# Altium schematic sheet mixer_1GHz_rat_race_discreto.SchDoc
size A4
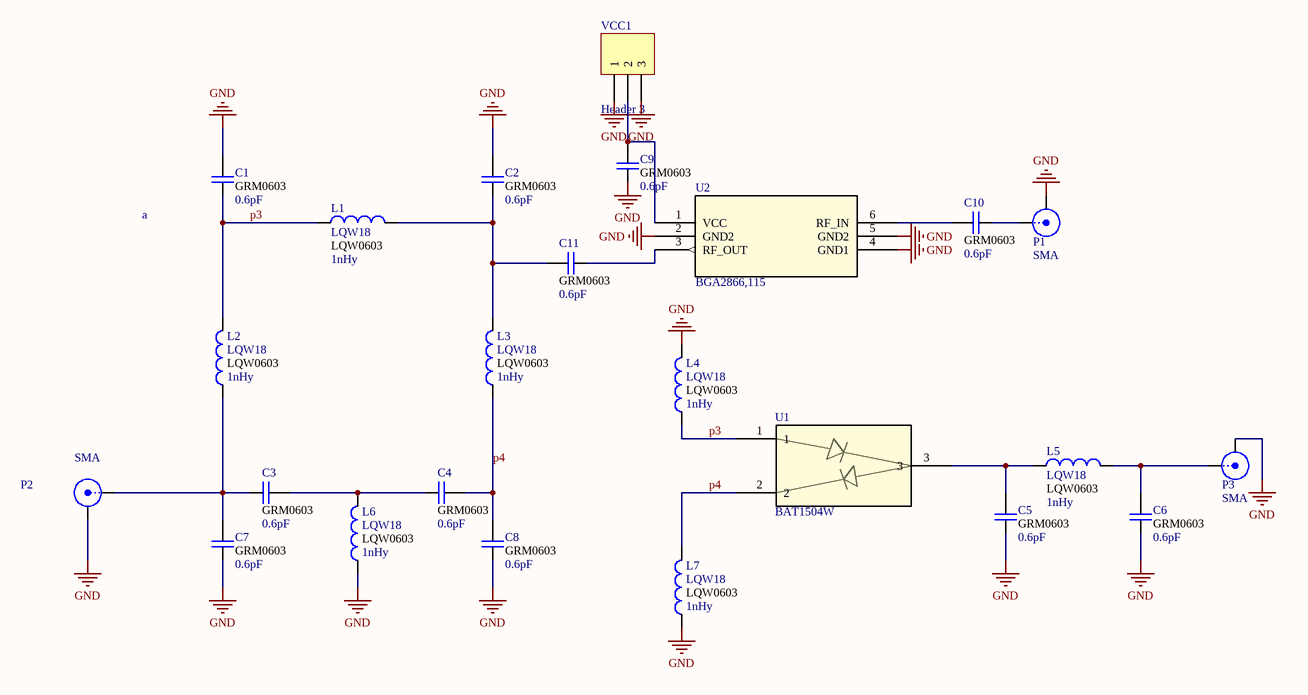
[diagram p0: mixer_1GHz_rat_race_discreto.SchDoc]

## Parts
C1  value 0.6pF  footprint: GRM0603  [CAPC1608X90N]  (hidden comment: Cap 0603)
C2  value 0.6pF  footprint: GRM0603  [CAPC1608X90N]  (hidden comment: Cap 0603)
C3  value 0.6pF  footprint: GRM0603  [CAPC1608X90N]  (hidden comment: Cap 0603)
C4  value 0.6pF  footprint: GRM0603  [CAPC1608X90N]  (hidden comment: Cap 0603)
C5  value 0.6pF  footprint: GRM0603  [CAPC1608X90N]  (hidden comment: Cap 0603)
C6  value 0.6pF  footprint: GRM0603  [CAPC1608X90N]  (hidden comment: Cap 0603)
C7  value 0.6pF  footprint: GRM0603  [CAPC1608X90N]  (hidden comment: Cap 0603)
C8  value 0.6pF  footprint: GRM0603  [CAPC1608X90N]  (hidden comment: Cap 0603)
C9  value 0.6pF  footprint: GRM0603  [CAPC1608X90N]  (hidden comment: Cap 0603)
C10  value 0.6pF  footprint: GRM0603  [CAPC1608X90N]  (hidden comment: Cap 0603)
C11  value 0.6pF  footprint: GRM0603  [CAPC1608X90N]  (hidden comment: Cap 0603)
L1  LQW18  value 1nHy  Parameter 1: LQW0603  [INDC1608X100N]
L2  LQW18  value 1nHy  Parameter 1: LQW0603  [INDC1608X100N]
L3  LQW18  value 1nHy  Parameter 1: LQW0603  [INDC1608X100N]
L4  LQW18  value 1nHy  Parameter 1: LQW0603  [INDC1608X100N]
L5  LQW18  value 1nHy  Parameter 1: LQW0603  [INDC1608X100N]
L6  LQW18  value 1nHy  Parameter 1: LQW0603  [INDC1608X100N]
L7  LQW18  value 1nHy  Parameter 1: LQW0603  [INDC1608X100N]
P1  SMA  [SMA-142-0701-851_V2]
P2  SMA  [SMA-142-0701-851_V2]
P3  SMA  [SMA-142-0701-851_V2]
U1  BAT1504W  [SOT_327XTSA1_INF]
U2  BGA2866,115  [SOT363_NXP]
VCC1  Header 3  [HDR1X3]

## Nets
GND: C1.2 C2.2 C5.1 C6.1 C7.1 C8.1 C9.1 L4.2 L6.1 L7.1 P1.2(Y) P2.2(Y) P3.2(Y) U2.2(GND2) U2.4(GND1) U2.5(GND2) VCC1.1 VCC1.3
p3: C1.1 L1.1 L2.2 L4.1 U1.1
p4: C4.2 C8.2 L3.1 L7.2 U1.2
NetC2_1: C2.1 C11.2 L1.2 L3.2
NetC3_1: C3.1 C7.2 L2.1 P2.1(X)
NetC3_2: C3.2 C4.1 L6.2
NetC5_2: C5.2 L5.1 U1.3
NetC6_2: C6.2 L5.2 P3.1(X)
NetC9_2: C9.2 U2.1(VCC) VCC1.2
NetC10_1: C10.1 P1.1(X)
NetC10_2: C10.2 U2.6(RF_IN)
NetC11_1: C11.1 U2.3(RF_OUT)

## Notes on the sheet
- a

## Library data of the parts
C1-C11 = Cap: Capacitor GRM18 0603
L1-L7 = LQW18: Ind RF Chip Wirewound 18nH 5% 100MHz 40Q-Factor 550mA 0603 Paper T/R; MP: LQW18AN18NJ00D
P1-P3 = SMB: SMB Straight Connector
U1 = BAT1504W: Diodo; Mfr_Name: Infineon
U2 = BGA2866,115: No Description Available; Mfr_Name: NXP
VCC1 = Header 3: Header, 3-Pin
